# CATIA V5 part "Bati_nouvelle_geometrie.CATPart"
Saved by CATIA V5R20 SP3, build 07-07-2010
Part number: Bati
Bounding box of the stored display mesh (mm): x -22 to 9, y -7 to 71, z -5 to 16
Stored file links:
  C:\Documents and Settings\Propriétaire\Mes documents\IFMA\COURS\PROJ IAO\CATIA\Bati_nouvelle_geometrie.CATPart
  C:\Documents and Settings\Propriétaire\Mes documents\IFMA\COURS\PROJ IAO\CATIA\Assemblage.CATProduct
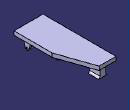
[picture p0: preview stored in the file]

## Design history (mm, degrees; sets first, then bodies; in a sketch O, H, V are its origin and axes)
Set1
  Plane1 to Plane3: linked copy from another document
  Point1: linked copy from another document
  Point2: linked copy from another document
  Line1: linked copy from another document
  Plane4: linked copy from another document
  Line2: linked copy from another document
  Line3: linked copy from another document
Body1 (main body)
  Sketch1 on Plane1, origin (0, 0, 0), H (0, 1, 0), V (0, 0, 1)
    arc A1 centre (0, 0) radius 2 from (-1.9365, -0.5) to (1.9365, -0.5) ccw
    point P1 (0, 0)
    point P2 (-1.9365, -0.5)
    point P3 (1.9365, -0.5)
    circle A2 centre (0, 0) radius 1
    point P4 (0, 0)
    line L1 (-1.9365, -0.5) -> (-5.164, 12)
    line L2 (5.164, 12) -> (-5.164, 12)
    line L3 (1.9365, -0.5) -> (5.164, 12)
    radius A1 = 2
    radius A2 = 1
    distance P3 H = 0.5
    distance H L2 = 12
    coincidence: O P1, P4 P1
    symmetry: P2 P3 V, L3 L1 V
    horizontal: L2 H
    tangency: L3 A1
  Pad1: profile Sketch1, direction (1, 0, 0), length 2
  Sketch2 on Plane2, origin (-3, 0, 0), H (0, 1, 0), V (0, 0, 1)
    projected arc E1 centre (0, 0) radius 2 from (-1.9365, -0.5) to (1.9365, -0.5) ccw from edge [face of Pad1 from Sketch1.A1 | end face of Pad1]
    projected line E2 (1.9365, -0.5) -> (5.164, 12) from edge [face of Pad1 from Sketch1.L3 | end face of Pad1]
    projected line E3 (5.164, 12) -> (-5.164, 12) from edge [face of Pad1 from Sketch1.L2 | end face of Pad1]
    projected line E4 (-5.164, 12) -> (-1.9365, -0.5) from edge [face of Pad1 from Sketch1.L1 | end face of Pad1]
    projected circle E5 centre (0, 0) radius 1 from edge [end face of Pad1 | face of Pad1 from Sketch1.A2]
  Pad2: profile Sketch2, direction (-1, 0, 0), length 2
  Sketch3 on Plane3, origin (-10, 0, 0), H (0, 1, 0), V (0, 0, 1)
    point P1 (23, 0)
    point P2 (58, 0)
    line L1 (58, 0) -> (58, 5)
    line L2 (58, 5) -> (69, 5)
    line L3 (23, 0) -> (23, 5)
    line L4 (23, 5) -> (12, 5)
    point P7 (58, 0)
    line L5 (58, 0) -> (69, 0)
    line L6 (69, 0) -> (69, 5)
    point P9 (23, 0)
    line L7 (23, 0) -> (12, 0)
    line L8 (12, 0) -> (12, 5)
    reference projected line E2 (58, 0) -> (30, 0) from Line1
    length L8 = 5
    distance L8 L3 = 11
    distance L6 L1 = 11
    distance L8 V = 12
    distance L1 V = 58
    vertical: L1 V, L3 V, L6 V, L8 V
    horizontal: L2 H, L4 H, L5 H, L7 H
    coincidence: L4 L2, L5 L7, P7 P2, L5 E2, P1 P9
  Shaft1: profile Sketch3, axis Line1, angle 360
  Sketch4 on face of Pad2 from Sketch2.E3, origin (0, 0, 12), H (1, 0, 0), V (0, 1, 0)
    line L1 (-22, 71) -> (9, 71)
    line L2 (9, 71) -> (9, -7)
    line L3 (9, -7) -> (-22, -7)
    line L4 (-22, -7) -> (-22, 71)
    length L2 = 78
    length L3 = 31
    distance V L2 = 9
    distance H L3 = 7
    horizontal: L1 H, L3 H
    vertical: L2 V, L4 V
  Pad3: profile Sketch4, direction (0, 0, 1), length 4
  Sketch5 on start face of Pad3, origin (0, 0, 12), H (1, 0, 0), V (0, -1, 0)
    reference projected line E1 (-15, -12) -> (-5, -12) from edge [face of Shaft1 from Sketch3.L4 | face of Shaft1 from Sketch3.L8]
    reference projected line E2 (-15, -23) -> (-5, -23) from edge [face of Shaft1 from Sketch3.L3 | face of Shaft1 from Sketch3.L4]
    point P5 (-13, -12)
    line L1 (-13, -12) -> (-7, -12)
    line L2 (-7, -12) -> (-7, -23)
    line L3 (-7, -23) -> (-13, -23)
    line L4 (-13, -23) -> (-13, -12)
    point P7 (-7, -23)
    point P9 (-9, -70)
    reference projected line E3 (-10, -58) -> (-10, -30) from Line1
    length L1 = 6
    coincidence: P5 E1, P7 E2
    horizontal: L1 H, L3 H
    vertical: L2 V, L4 V
    symmetry: L2 L4 E3
  Pad4: profile Sketch5, direction (0, 0, -1), up to face of Shaft1 from Sketch3.L4
  Sketch6 on start face of Pad3, origin (0, 0, 12), H (1, 0, 0), V (0, -1, 0)
    reference projected line E2 (-13, -12) -> (-13, -23) from edge [start face of Pad3 | face of Pad4 from Sketch5.L4]
    reference projected line E3 (-7, -23) -> (-7, -12) from edge [start face of Pad3 | face of Pad4 from Sketch5.L2]
    reference projected line E5 (-15, -58) -> (-5, -58) from edge [face of Shaft1 from Sketch3.L2 | face of Shaft1 from Sketch3.L1]
    reference projected line E6 (-15, -69) -> (-5, -69) from edge [face of Shaft1 from Sketch3.L6 | face of Shaft1 from Sketch3.L2]
    line L1 (-13, -58) -> (-7, -58)
    line L2 (-7, -58) -> (-7, -69)
    line L3 (-7, -69) -> (-13, -69)
    line L4 (-13, -69) -> (-13, -58)
    horizontal: L1 H, L3 H
    vertical: L2 V, L4 V
    coincidence: L1 E5, L3 E6, L2 E3, L4 E2
  Pad5: profile Sketch6, direction (0, 0, -1), up to face of Shaft1 from Sketch3.L2
  Sketch7 on Plane4, origin (0, 44, 0), H (1, 0, 0), V (0, 0, 1)
    line L1 (-12, 2) -> (-8, 2)
    line L2 (-8, 2) -> (-8, -2)
    line L3 (-8, -2) -> (-12, -2)
    line L4 (-12, -2) -> (-12, 2)
    reference projected line E1 (-10, 0) -> (10, 0) from Line2
    reference projected line E2 (-10, 10) -> (-10, -10) from Line3
    length L2 = 4
    length L1 = 4
    horizontal: L1 H, L3 H
    vertical: L2 V, L4 V
    symmetry: L1 L3 E1, L2 L4 E2
  Pocket1: profile Sketch7, direction (0, 1, 0), length 21
  Pocket2: profile Sketch7, direction (0, -1, 0), length 28
  Sketch8 on start face of Pad3, origin (0, 0, 12), H (1, 0, 0), V (0, -1, 0)
    point P1 (11, -28)
    line L1 (11, -28) -> (-7, -80)
    point P2 (-7, -80)
    line L2 (-7, -80) -> (17.9327, -86.4036)
    line L3 (17.9327, -86.4036) -> (11, -28)
    reference projected line E1 (9, 7) -> (9, -71) from edge [start face of Pad3 | face of Pad3 from Sketch4.L2]
    reference projected line E2 (9, 7) -> (9, -71) from edge [start face of Pad3 | face of Pad3 from Sketch4.L2]
    reference projected line E3 (9, -71) -> (-22, -71) from edge [start face of Pad3 | face of Pad3 from Sketch4.L1]
    distance E1 P2 = 16
    distance P1 E2 = 2
    distance P1 E3 = 43
  Pocket3: profile Sketch8, direction (0, 0, 1), through (limit type 3)
  Sketch9 on face of Pad5, origin (0, 58, 0), H (1, 0, 0), V (0, 0, 1)
    line L1 (-29.4999, 2) -> (0.5001, 2)
    line L2 (0.5001, 2) -> (0.5001, -28)
    line L3 (0.5001, -28) -> (-29.4999, -28)
    line L4 (-29.4999, -28) -> (-29.4999, 2)
    distance L1 H = 2
    horizontal: L1 H, L3 H
    vertical: L2 V, L4 V
  Pocket4: profile Sketch9, direction (0, 1, 0), through (limit type 3)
